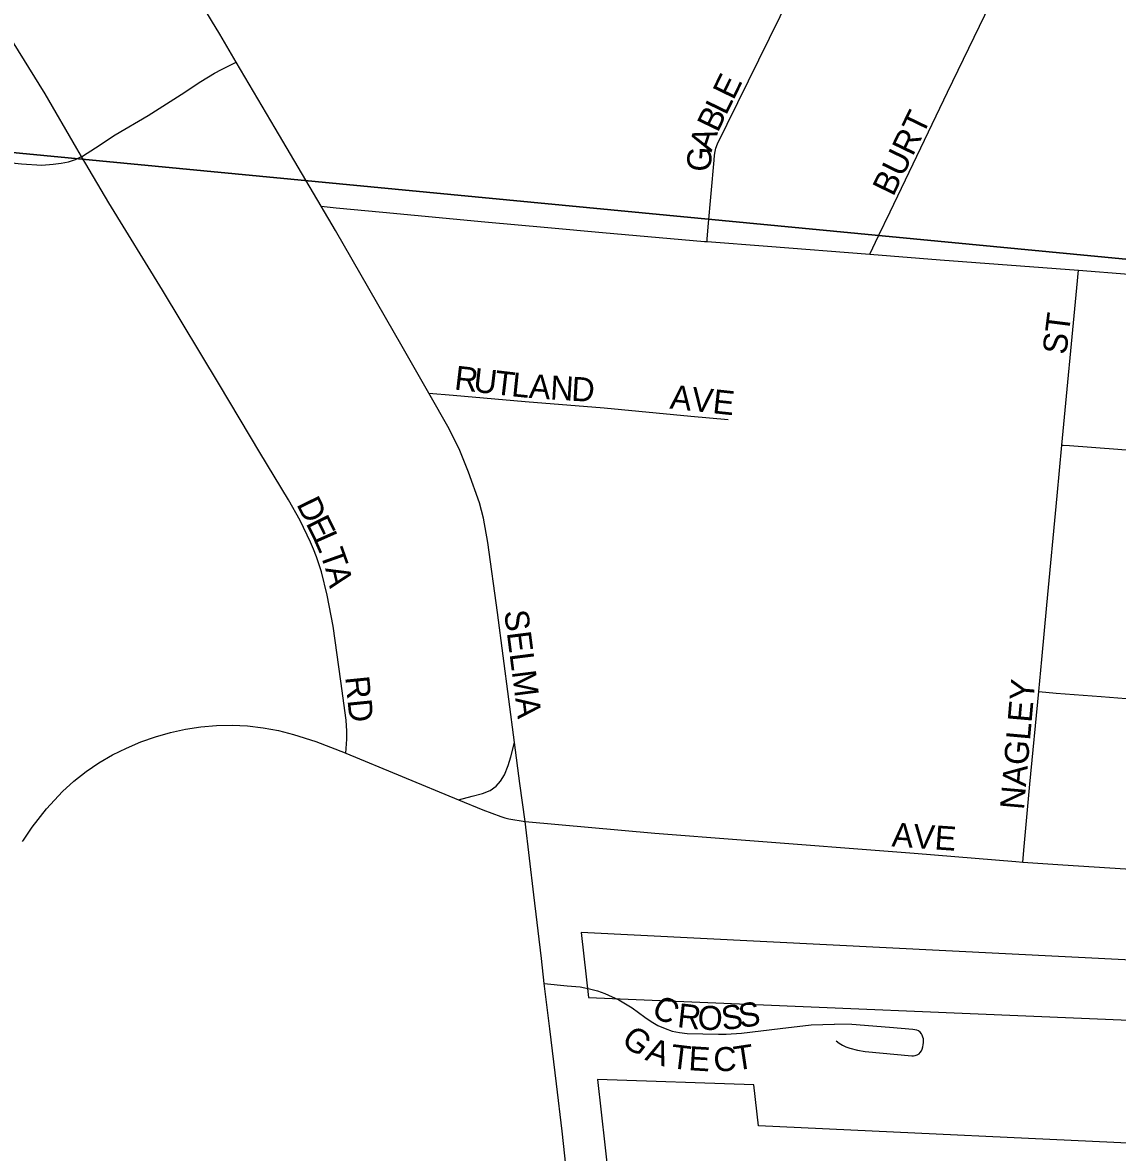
# Model space of a CAD drawing. Extents: x 1410790 to 1770854, y 566777 to 831614.
# Drawn here: x 1605056 to 1607334, y 695774 to 698124 of the extents above; entities that cross this region are included whole.
import ezdxf

# ---------------------------------------------------------------- set-up
doc = ezdxf.new("R2010")
doc.units = 0
for name, color, linetype in [('GM_X_City_Street', 7, 'Continuous'), ('GM_X_City_Street_Text', 7, 'Continuous'), ('GM_X_Corporation', 7, 'Continuous'), ('GM_X_County_Road', 7, 'Continuous'), ('GM_X_Section', 7, 'Continuous')]:
    doc.layers.add(name, color=color, linetype=linetype)

msp = doc.modelspace()

# ---------------------------------------------------------------- linework, layer by layer
at = {"layer": 'GM_X_City_Street'}
for points in [[(1606480, 697668.3), (1606480.4, 697673.2), (1606482.4, 697698.8), (1606494.5, 697837.8), (1606495.5, 697848.4), (1606496.9, 697856), (1606498.4, 697862.4), (1606501.8, 697871.4), (1606522, 697912.8), (1606632.1, 698136.8), (1606688.6, 698255.2), (1606748.9, 698380.1)], [(1605178.8, 697845.3), (1605169, 697862.3), (1605103.4, 697975.9), (1604982.7, 698169.4), (1604942.5, 698234.5), (1604931.2, 698252.7)], [(1606818.5, 697642.1), (1606836.7, 697680.1), (1606860.8, 697730.3), (1606980.5, 697979.1), (1607091.2, 698208.9)], [(1605500.4, 698041.7), (1605466.3, 698099.7), (1605449, 698128.3), (1605424.6, 698168.4)], [(1605178.8, 697845.3), (1605180.6, 697846.2), (1605208, 697863.4), (1605248.7, 697890.3), (1605317.3, 697930.5), (1605386, 697974.1), (1605427, 698001.4), (1605455.4, 698018.4), (1605470.1, 698026), (1605500.4, 698041.7)], [(1605677.6, 697741.8), (1605581.5, 697904.1), (1605500.4, 698041.7)], [(1604949.2, 697841.1), (1604958.9, 697840), (1605053.6, 697830.3), (1605096.5, 697827), (1605119.6, 697829.2), (1605136.4, 697831.2), (1605151.9, 697833.9), (1605166.5, 697839), (1605178.8, 697845.3)], [(1605728.5, 696604.7), (1605730.7, 696633.4), (1605730.7, 696650.2), (1605729.3, 696673.3), (1605718, 696754.4), (1605702.1, 696868.5), (1605689.9, 696933.2), (1605677.8, 696981.3), (1605667.5, 697012.8), (1605661.4, 697028.7), (1605655, 697043.5), (1605633.4, 697088.1), (1605609.6, 697131.4), (1605549.7, 697229.6), (1605465.9, 697370.7), (1605347.3, 697567.6), (1605235.3, 697749.3), (1605178.8, 697845.3)], [(1605677.6, 697741.8), (1605708.2, 697738.9), (1605805.4, 697729.6), (1606017.9, 697709.7), (1606148.5, 697697.6), (1606262.8, 697687.3), (1606474.9, 697668.7), (1606480, 697668.3)], [(1605901.6, 697352.9), (1605846, 697450.5), (1605707.4, 697691.6), (1605677.6, 697741.8)], [(1606480, 697668.3), (1606605.6, 697658.7), (1606818.5, 697642.1)], [(1606818.5, 697642.1), (1606965.3, 697630.6), (1607252.6, 697608.8)], [(1607218.2, 697245.2), (1607249.1, 697572.2), (1607252.6, 697608.8)], [(1607252.6, 697608.8), (1607357.5, 697600.8), (1607521, 697588.2), (1607651.7, 697577.6), (1607864.1, 697560.6), (1607878.1, 697559.5)], [(1605901.6, 697352.9), (1605951.6, 697348.7), (1606101.7, 697336), (1606265.8, 697322.3), (1606446.4, 697305.4), (1606524.1, 697298.2)], [(1606079.4, 696626.7), (1606044, 696896.9), (1606023.7, 697042.8), (1606014.7, 697092.9), (1606006.4, 697125.3), (1605983.6, 697188.7), (1605965.4, 697233.9), (1605943.6, 697279.1), (1605901.6, 697352.9)], [(1607170.2, 696732.4), (1607176.6, 696799), (1607187.2, 696912.5), (1607208.2, 697139.6), (1607218.2, 697245.2)], [(1607218.2, 697245.2), (1607221.1, 697245), (1607234.1, 697244.2), (1607334.7, 697236.8), (1607429.4, 697229.2), (1607571.2, 697217.6), (1607574.1, 697217.4)], [(1607137.1, 696378.1), (1607140, 696410.1), (1607151.7, 696539.8), (1607170.2, 696732.4)], [(1607170.2, 696732.4), (1607206.4, 696729), (1607299.6, 696722.4), (1607524.9, 696704.5)], [(1605056.2, 696421.1), (1605057.8, 696423.8), (1605076, 696450.6), (1605106.2, 696488.8), (1605139.3, 696524.4), (1605163.1, 696546.3), (1605188.3, 696566.5), (1605215, 696584.7), (1605242.9, 696601), (1605272, 696615.2), (1605301.9, 696627.7), (1605332.5, 696638.4), (1605363.7, 696647.2), (1605395.3, 696654.1), (1605427.3, 696659), (1605459.6, 696661.9), (1605491.9, 696662.6), (1605524.2, 696661.1), (1605556.3, 696657.3), (1605588.2, 696651.4), (1605619.6, 696643.5), (1605665.9, 696628.6), (1605726.9, 696605.4), (1605728.5, 696604.7)], [(1606101.6, 696462.7), (1606090.6, 696541.4), (1606079.4, 696626.7)], [(1605728.5, 696604.7), (1605963.2, 696507.6)], [(1605963.2, 696507.6), (1606013.9, 696486.6), (1606051.2, 696472.7), (1606059.7, 696469.9), (1606067.8, 696468), (1606101.6, 696462.7)], [(1606141.5, 696125.3), (1606135.4, 696177.4), (1606119.6, 696309.6), (1606101.6, 696462.7)], [(1606101.6, 696462.7), (1606371.5, 696438.2), (1606551.2, 696424.4), (1606910.7, 696396.7), (1607122.6, 696379.2), (1607137.1, 696378.1)], [(1607137.1, 696378.1), (1607219.9, 696372.2), (1607350.5, 696363.9), (1607513.7, 696350.5), (1607709.7, 696335.3), (1607782.1, 696329.8)], [(1606141.5, 696125.3), (1606188.8, 696120.9), (1606216.4, 696118.2), (1606235.6, 696114.7), (1606252.4, 696109.9), (1606267.5, 696104.7), (1606296.6, 696091.2), (1606324.2, 696074.5), (1606350.6, 696055.6), (1606363.9, 696046.4), (1606377.9, 696038.4), (1606392.6, 696031.7), (1606407.6, 696026.6), (1606422.7, 696023.2), (1606438.4, 696021.7), (1606503.5, 696020), (1606519.7, 696020.3), (1606551.9, 696022.3), (1606632.3, 696032.1), (1606696.5, 696039.2), (1606745.2, 696040.9)], [(1606233.6, 695363.6), (1606217.2, 695493.5), (1606205.4, 695590.4), (1606189.2, 695722.2), (1606178.9, 695818.1), (1606166.8, 695916.7), (1606152.7, 696031.2), (1606141.5, 696125.3)], [(1606748.5, 696006.3), (1606754.9, 696001.5), (1606761.9, 695997.3), (1606768.4, 695993.9), (1606777, 695991.1), (1606792.7, 695987.1), (1606808.7, 695984.1), (1606905.8, 695975), (1606909.3, 695975.2), (1606913.2, 695975.7), (1606917.4, 695977), (1606921, 695979.4), (1606923.7, 695982.2), (1606925.9, 695985.1), (1606927.6, 695989.1), (1606929.1, 695993.7), (1606929.9, 695998.1), (1606930.4, 696002.5), (1606930.1, 696010.2), (1606929.1, 696014), (1606927.8, 696017.9), (1606926, 696021), (1606923.6, 696024.3), (1606920.2, 696026.7), (1606916.3, 696028.3), (1606908.3, 696029.6), (1606859.8, 696034.2), (1606780.9, 696040.5), (1606745.2, 696040.9)]]:
    msp.add_lwpolyline(points, dxfattribs=at)
at = {"layer": 'GM_X_Corporation'}
msp.add_lwpolyline([(1606218.3, 696231.3), (1606233.3, 696096.4), (1607490.6, 696043.7), (1607474, 695787.9), (1606587.2, 695829.6), (1606577.2, 695914.6), (1606252.3, 695926), (1606297.6, 695518.4), (1606375.8, 695507.4), (1606667.6, 695497.2), (1606689.5, 695494.9), (1606729.5, 695668.3), (1606974.2, 695655.5), (1607570.9, 695617.4), (1607610.9, 696161.2)], close=True, dxfattribs=at)
at = {"layer": 'GM_X_County_Road'}
msp.add_lwpolyline([(1605963.2, 696507.6), (1605991.2, 696514.8), (1606012.6, 696520.3), (1606028.8, 696526.5), (1606041.2, 696535.5), (1606050.6, 696546.2), (1606058.5, 696559.3), (1606066.4, 696578.6), (1606072, 696596.5), (1606079.4, 696626.7)], dxfattribs=at)
at = {"layer": 'GM_X_Section'}
for points in [[(1604192.4, 703233.9), (1609553.2, 702682.3), (1609051.7, 697468.6), (1603688.3, 697982.3)], [(1609051.7, 697468.6), (1608507.1, 692045.6), (1603189.9, 692572.7), (1603688.3, 697982.3)]]:
    msp.add_lwpolyline(points, close=True, dxfattribs=at)

# ---------------------------------------------------------------- texts
at = {"layer": 'GM_X_City_Street_Text'}
for s, rotation, p in [('E', 64.0703, (1606534.9, 697960.8)), ('L', 64.1009, (1606519.5, 697929.2)), ('B', 64.331, (1606502.3, 697893.5)), ('BURT', 64.1305, (1606867.2, 697760.5)), ('A', 71.5858, (1606489.1, 697853.3)), ('G', 87.5949, (1606487.9, 697813)), ('ST', 82.8783, (1607227.2, 697431.9)), ('R', 353.3178, (1605952.8, 697360.9)), ('U', 353.3274, (1605992.2, 697356.3)), ('T', 353.3189, (1606035.9, 697351.2)), ('L', 354.1339, (1606071.6, 697347)), ('A', 356.1478, (1606108.5, 697343.3)), ('N', 356.5419, (1606152.8, 697340.3)), ('D', 356.5341, (1606196.7, 697337.6)), ('AVE', 353.8848, (1606401.4, 697321.3)), ('D', 296.2621, (1605625.1, 697122.3)), ('E', 296.2693, (1605644.6, 697082.9)), ('L', 293.9375, (1605660, 697051.8)), ('T', 289.6143, (1605673.9, 697020.5)), ('A', 283.2756, (1605685.3, 696988.8)), ('SELMA', 277.2755, (1606057.8, 696899.5)), ('RD', 275.7182, (1605727.2, 696762.8)), ('NAGLEY', 84.9857, (1607139.1, 696485.6)), ('AVE', 356.0569, (1606863.2, 696410.6)), ('C', 330.6753, (1606361.5, 696061)), ('R', 353.5239, (1606416.6, 696034.9)), ('O', 357.1106, (1606459.4, 696030.2)), ('S', 6.7595, (1606512.5, 696028.3)), ('S', 8.9159, (1606549.5, 696032.7)), ('G', 322.0503, (1606299.2, 696002.7)), ('A', 340.4819, (1606349.2, 695967.2)), ('T', 353.1519, (1606402.4, 695949.8)), ('E', 356.4818, (1606440.5, 695945.3)), ('C', 2.0242, (1606494.1, 695942.4)), ('T', 8.5712, (1606539.9, 695944.3))]:
    msp.add_text(s, height=50, rotation=rotation, dxfattribs=at).set_placement(p)

doc.saveas('drawing.dxf')
